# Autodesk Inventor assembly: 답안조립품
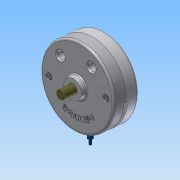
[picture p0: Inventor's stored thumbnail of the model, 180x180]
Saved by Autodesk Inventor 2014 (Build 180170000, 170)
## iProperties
Created: 2015-06
Part Number: 답안조립품
Document SubType Name: Assembly
Designer: Administrator
Author: Administrator
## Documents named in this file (10)
- C:\Documents and Settings\Administrator\바탕 화면\450631V1014\답안조립품.iam
- C:\Documents and Settings\Administrator\바탕 화면\450631V1014\1-본체.ipt
- C:\Documents and Settings\Administrator\바탕 화면\450631V1014\베어링62_22.ipt
- C:\Documents and Settings\Administrator\바탕 화면\450631V1014\덮개.ipt
- C:\Documents and Settings\Administrator\바탕 화면\450631V1014\축.ipt
- C:\Documents and Settings\Administrator\바탕 화면\450631V1014\멈춤링.ipt
- C:\Documents and Settings\Administrator\바탕 화면\450631V1014\슬라이더2.ipt
- C:\Documents and Settings\Administrator\바탕 화면\450631V1014\슬라이더.ipt
- C:\Documents and Settings\Administrator\바탕 화면\450631V1014\M10x35.ipt
- C:\Documents and Settings\Administrator\바탕 화면\450631V1014\평행핀.ipt
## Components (8 placed, 5 different names)
1. 1-본체:1
2. KS B 2023 62/22 - 22 x 50 x 14:1
3. KS B 2023 62/22 - 22 x 50 x 14:2
4. KS B 1336 22 x 1.2:1
5. KS B 1336 22 x 1.2:2
6. KS B 1003 - 미터 M 10 x 35:1
7. KS B 1003 - 미터 M 10 x 35:2
8. KS B 1320 B B 5 x  20:1
